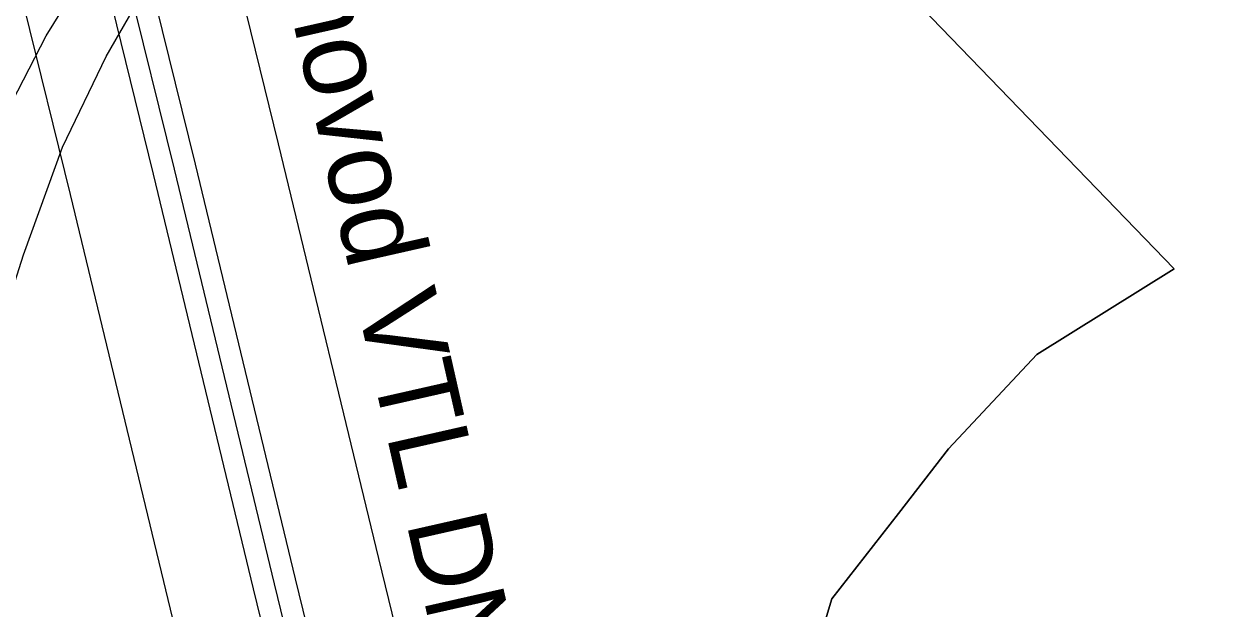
# Model space of a CAD drawing. Extents: x -555887 to -552101, y -1100251 to -1096546.
# Drawn here: x -553613.1 to -553387.4, y -1097242.4 to -1097133.2 of the extents above; entities that cross this region are included whole.
import ezdxf

# ---------------------------------------------------------------- set-up
doc = ezdxf.new("R2010")
doc.units = 0
for name, color, linetype in [('07_OCH_P A POPISY TI', 7, 'Continuous'), ('07_PLYNOVOD', 7, 'Continuous'), ('vrstevnice', 7, 'Continuous'), ('zájem', 7, 'Continuous')]:
    doc.layers.add(name, color=color, linetype=linetype)

msp = doc.modelspace()

# ---------------------------------------------------------------- linework, layer by layer
at = {"layer": '07_OCH_P A POPISY TI'}
for points in [[(-553574.22, -1097120.44), (-553565.59, -1097155.54), (-553546.89, -1097233), (-553525.62, -1097320.01), (-553504.5, -1097404.57), (-553504.46, -1097404.75), (-553494.23, -1097444.77), (-553477.77, -1097515.86), (-553477.7, -1097516.11), (-553477.38, -1097517.2), (-553477, -1097519.43), (-553476.87, -1097521.68), (-553476.99, -1097523.94), (-553477.18, -1097525.06), (-553488.78, -1097593.15), (-553503.72, -1097682.07)], [(-553589.76, -1097124.22), (-553581.13, -1097159.32), (-553562.43, -1097236.78), (-553541.16, -1097323.85), (-553520.01, -1097408.5), (-553519.96, -1097408.72), (-553509.77, -1097448.55), (-553493.26, -1097519.9), (-553493.06, -1097520.58), (-553492.93, -1097521.02), (-553492.88, -1097521.92), (-553492.96, -1097522.37), (-553504.56, -1097590.48), (-553519.48, -1097679.31)], [(-553527.36, -1097677.93), (-553512.44, -1097589.14), (-553501, -1097521.94), (-553501, -1097521.92), (-553517.55, -1097450.45), (-553527.71, -1097410.71), (-553527.77, -1097410.46), (-553548.92, -1097325.77), (-553570.21, -1097238.66), (-553588.91, -1097161.22), (-553597.54, -1097126.12)], [(-553543.12, -1097675.17), (-553528.22, -1097586.47), (-553517.31, -1097522.42), (-553533.09, -1097454.23), (-553543.21, -1097414.67), (-553543.28, -1097414.39), (-553564.46, -1097329.61), (-553585.76, -1097242.44), (-553604.45, -1097165.01), (-553613.08, -1097129.9)]]:
    msp.add_lwpolyline(points, dxfattribs=at)
at = {"layer": '07_PLYNOVOD'}
msp.add_lwpolyline([(-553585.25, -1098028.34), (-553568.13, -1097932.52), (-553553.96, -1097851.86), (-553539.25, -1097765.27), (-553523.42, -1097678.62), (-553508.5, -1097589.81), (-553496.9, -1097521.7), (-553497.13, -1097520.91), (-553513.66, -1097449.5), (-553523.83, -1097409.71), (-553523.89, -1097409.48), (-553545.04, -1097324.81), (-553566.32, -1097237.72), (-553585.02, -1097160.27), (-553593.65, -1097125.17), (-553614.64, -1097037.99), (-553634.86, -1096953.32), (-553647.66, -1096902.46)], dxfattribs=at)
at = {"layer": 'vrstevnice'}
for points in [[(-553639.97, -1097218.52), (-553628.51, -1097187.36), (-553621.66, -1097159.86), (-553609, -1097135.32), (-553596.91, -1097115.83), (-553561.93, -1097073.8), (-553549.75, -1097054.11), (-553538.05, -1097027.22), (-553522.03, -1097005.66), (-553512.66, -1096995.33), (-553496.65, -1096980.64), (-553483.88, -1096971.28), (-553471.27, -1096959.01), (-553459.63, -1096948.68), (-553449.88, -1096934.99), (-553443.99, -1096922.83), (-553431.41, -1096907.72), (-553397.8, -1096886.72), (-553391.12, -1096882.2), (-553375.79, -1096871.02), (-553361.64, -1096865.72)], [(-553748.86, -1097128.23), (-553737.63, -1097176.81), (-553732.71, -1097192.54), (-553724.99, -1097211.78), (-553718.81, -1097223.85), (-553710.81, -1097235.23), (-553705.05, -1097241.69), (-553699.44, -1097246.46), (-553688.2, -1097253.2), (-553675, -1097257.83), (-553667.14, -1097257.97), (-553657.31, -1097255.73), (-553653.38, -1097253.2), (-553645.8, -1097246.04), (-553638.21, -1097237.19), (-553633.58, -1097230.17), (-553626.7, -1097216.27), (-553622.63, -1097205.74), (-553613.22, -1097176.25), (-553605.92, -1097156.17), (-553597.78, -1097139.18), (-553591.04, -1097127.53)]]:
    msp.add_lwpolyline(points, dxfattribs=at)
at = {"layer": 'zájem'}
for points in [[(-553468.26, -1097427.51), (-553470.27, -1097387.64), (-553478.35, -1097327.08), (-553478.33, -1097321.05), (-553478.29, -1097304.84), (-553474.66, -1097286.22), (-553472.4, -1097277.72), (-553465.14, -1097250.39), (-553462.14, -1097240.5), (-553449.73, -1097224.56), (-553440.34, -1097212.5), (-553423.88, -1097194.88), (-553398.19, -1097178.87), (-553454.37, -1097120.74)], [(-553454.37, -1097120.74), (-553398.19, -1097178.87), (-553423.88, -1097194.88), (-553440.34, -1097212.5), (-553449.73, -1097224.56), (-553462.14, -1097240.5), (-553465.14, -1097250.39), (-553472.4, -1097277.72), (-553474.66, -1097286.22), (-553478.29, -1097304.84), (-553478.33, -1097321.05), (-553478.35, -1097327.08), (-553470.27, -1097387.64), (-553468.26, -1097427.51)]]:
    msp.add_lwpolyline(points, dxfattribs=at)

# ---------------------------------------------------------------- texts
at = {"layer": '07_PLYNOVOD'}
msp.add_text('plynovod VTL DN 150', height=15, rotation=282.7547, dxfattribs=at).set_placement((-553570.02, -1097101.12))

doc.saveas('drawing.dxf')
